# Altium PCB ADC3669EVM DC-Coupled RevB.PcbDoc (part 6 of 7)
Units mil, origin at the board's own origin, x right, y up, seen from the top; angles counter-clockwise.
Board outline 5000 x 2716.54 mil, 12 copper layers (Top Layer, L2 GND, L3 SIG, L4 GND, L5 PWR, L6 GND, L7 GND, L8 PWR, L9 GND, L10 PWR, L11 GND, Bottom Layer), stack 61 mil thick; 546 components, 341 nets, 2088 pads, 1256 vias.
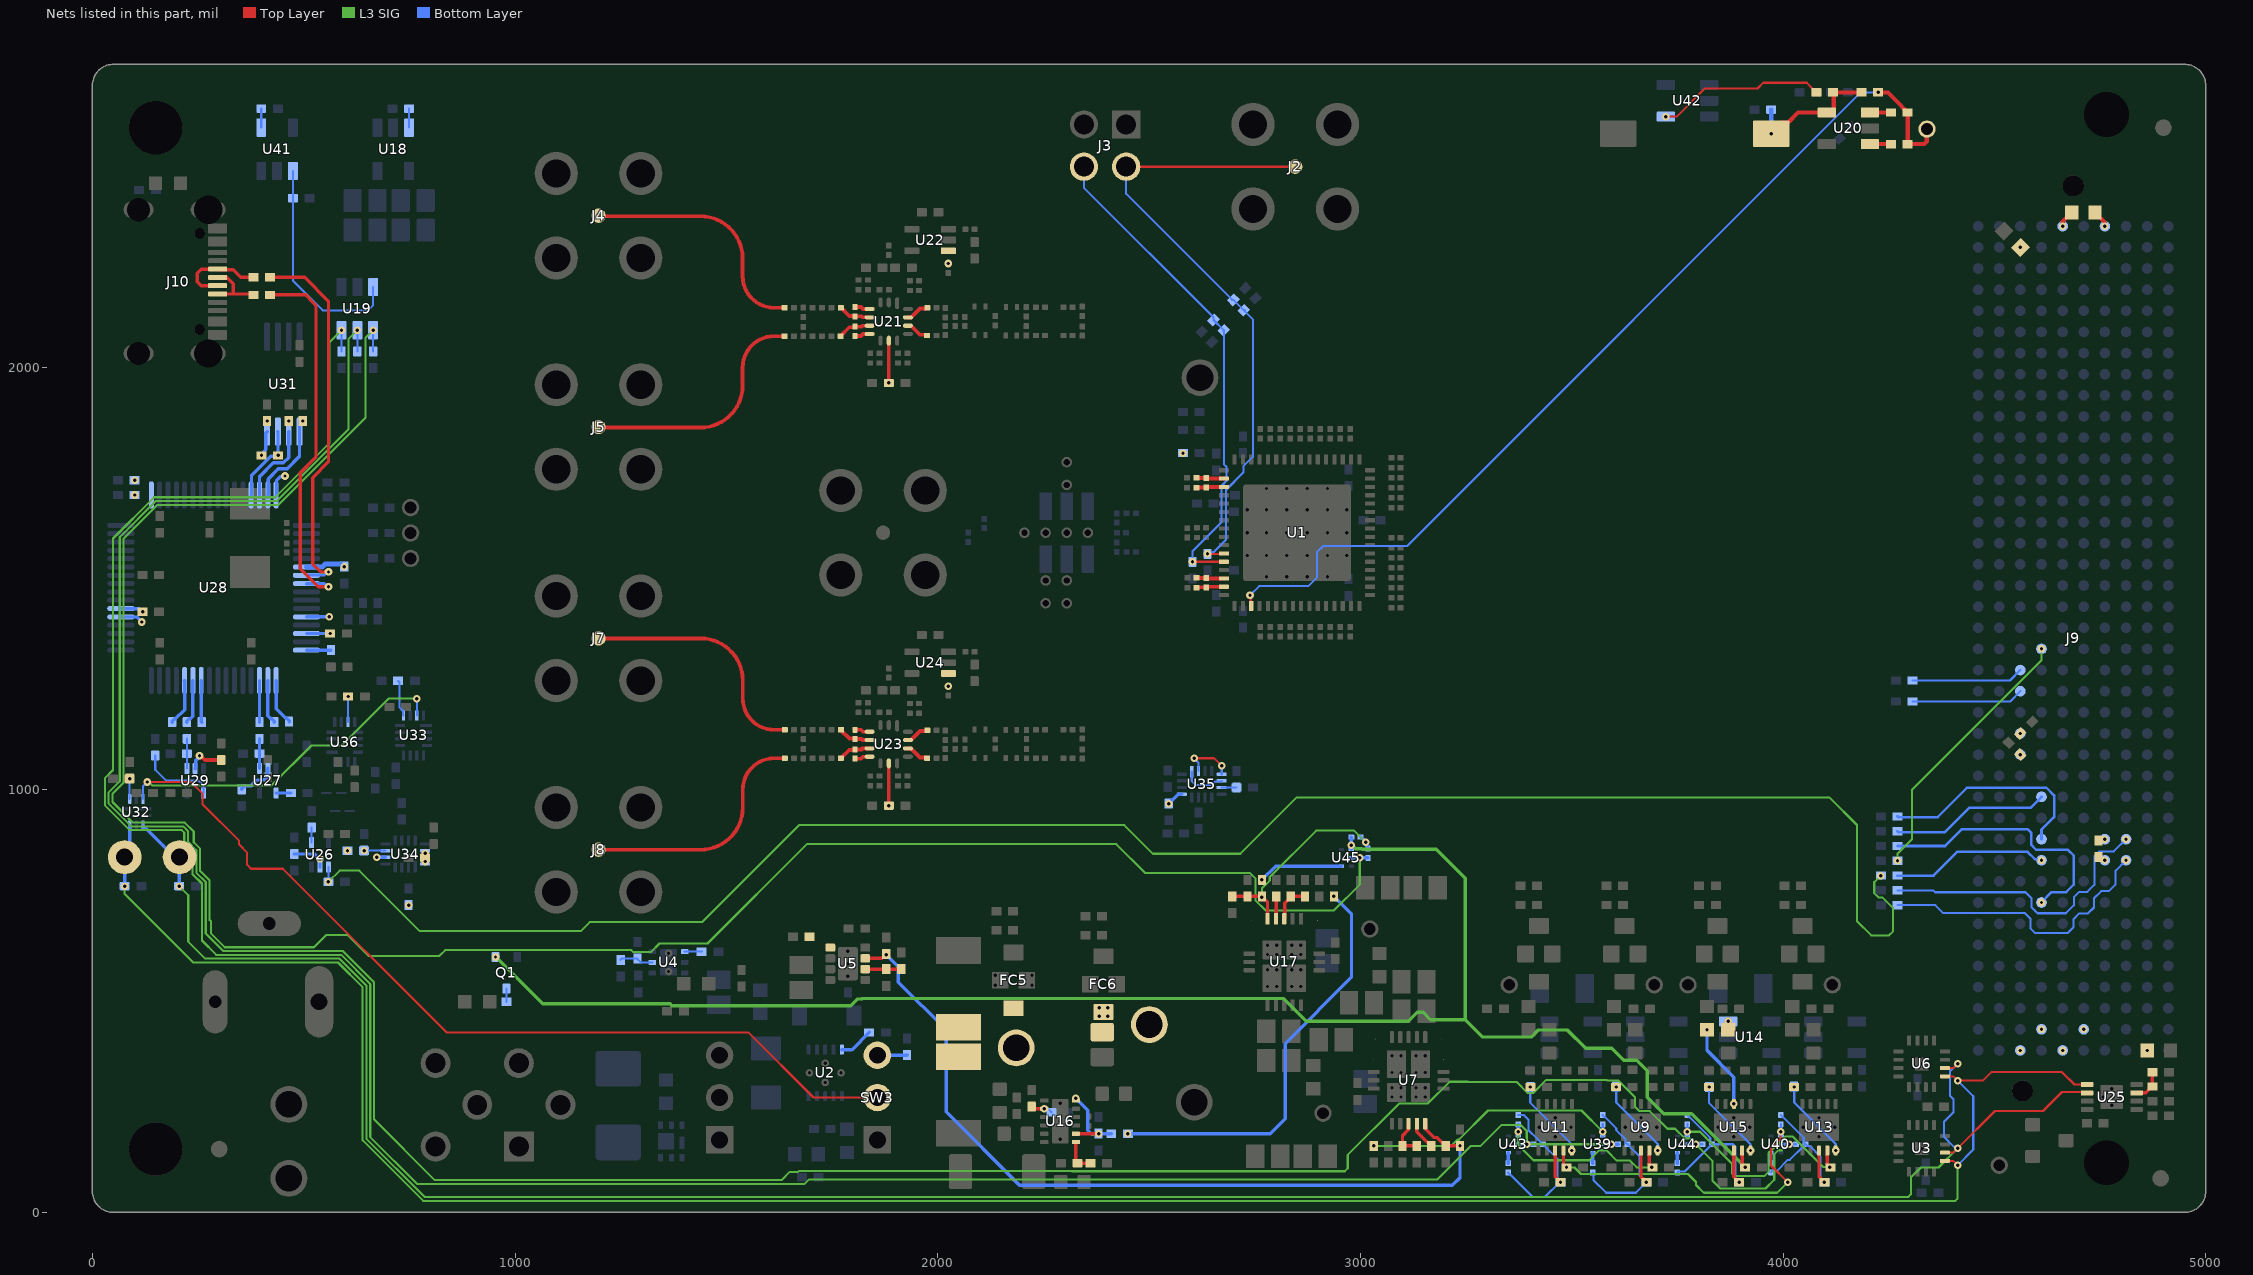
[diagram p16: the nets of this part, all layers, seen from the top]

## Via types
v1: diameter 18, hole 8, Top Layer to Bottom Layer, tented both sides, 1256 vias

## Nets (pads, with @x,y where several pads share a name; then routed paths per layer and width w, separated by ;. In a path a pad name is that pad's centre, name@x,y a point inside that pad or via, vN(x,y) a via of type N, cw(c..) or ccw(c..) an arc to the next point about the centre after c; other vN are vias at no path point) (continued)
NetFB6_1: FB6.1 R46.1 U14.3 U15.8 | length 221.5
  Top Layer w18: R46.1@3870.14,432.35 v1(3870.14,452.04)
  Bottom Layer w8: v1(3820.14,432.35) 3820.14,383.17 3883.53,319.79 v1(3883.53,256.76)
NetFC5_1: FC5.1 R54.1 R58.2 TP9.1
NetFC6_1: FC6.1 R59.2 TP8.1
  other v1: 2382,464.15 2402,464.15 2382,484.15 2402,484.15
NetJ2_1: J2.1 J3.2 R111.1 R112.2 R122.1 U1.27 | length 1534.2
  Top Layer w5: J3.2@2445.89,2474.15 J2.1@2845.89,2474.15 ; v1(2638.33,1558.27) 2675.98,1558.27 U1.27@2676.77,1559.06
  Bottom Layer w5: J3.2@2445.89,2474.15 2445.89,2409.81 2696.65,2159.05 R112.2@2699.5,2159.05 R122.1@2723.77,2134.78 ; v1(2638.33,1558.27) 2642.74,1562.68 2652.74,1562.68 2681.87,1591.81 2681.87,1709.17 2723.23,1750.53 2723.23,1765.27 2745.57,1787.61 2745.57,2112.98 R122.1@2723.77,2134.78 ; R122.1@2727.22,2134.78 R122.1@2723.77,2134.78
NetJ3_4: J3.4 R113.2 R121.2 R123.1 U1.28 | length 1181.2
  Top Layer w5: v1(2602.87,1539.37) U1.28@2676.77,1539.37
  Bottom Layer w5: J3.4@2345.89,2474.15 2345.89,2424.15 2652.34,2117.7 R123.1@2652.34,2111.49 R113.2@2676.61,2087.22 R113.2@2676.61,2084.44 ; v1(2602.87,1539.37) 2602.87,1564.5 2671.27,1632.89 2671.27,1718.86 2683.35,1730.94 2683.35,1764.05 2677.03,1770.36 R113.2@2677.03,2084.01
NetJ4_1: J4.1 R147.1 | length 581.1
  Top Layer w9: J4.1@1198.17,2356.89 1438.46,2356.89 cw(c1438.46,2256.89) 1538.46,2256.89 1538.46,2214.96 ccw(c1612.83,2214.96) 1612.83,2140.59 R147.1@1637.78,2140.59
NetJ5_1: J5.1 R140.1 | length 581.1
  Top Layer w9: J5.1@1198.17,1856.89 1438.46,1856.89 ccw(c1438.46,1956.89) 1538.46,1956.89 1538.46,1998.82 cw(c1612.83,1998.82) 1612.83,2073.19 R140.1@1637.78,2073.19
NetJ7_1: J7.1 R166.1 | length 582.1
  Top Layer w9: J7.1@1197.5,1358.27 1438.86,1358.27 cw(c1438.86,1258.27) 1538.86,1258.27 1538.86,1216.34 ccw(c1613.23,1216.34) 1613.23,1141.97 R166.1@1638.18,1141.97
NetJ8_1: J8.1 R159.1 | length 582.1
  Top Layer w9: J8.1@1197.5,858.27 1438.86,858.27 ccw(c1438.86,958.27) 1538.86,958.27 1538.86,1000.2 cw(c1613.23,1000.2) 1613.23,1074.57 R159.1@1638.18,1074.57
NetJ9_B40: J9.B40 R182.2
  other v1: 4861.42,383.27
NetJ9_C30: J9.C30 R180.2 | length 698.8
  Bottom Layer w5: R180.2@4270.69,762 4355.65,762 4360.11,757.54 4573.56,757.54 4587.87,743.23 4587.87,722.12 4602.07,707.92 4669.02,707.92 4688.01,726.9 4688.01,745.91 4700.55,758.45 4719.92,758.45 4736.51,775.05 4736.51,842.58 4748.32,854.39 4782.54,854.39 v1(4811.42,883.27)
NetJ9_C31: J9.C31 R181.2 | length 695.4
  Bottom Layer w5: R181.2@4270.69,727 4360.05,727 4378.74,708.31 4572.43,708.31 4585.17,695.57 4585.17,672.37 4596.73,660.8 4673,660.8 4686.96,674.76 4686.96,693.63 4700.89,707.56 4721.5,707.56 4735.57,721.63 4735.57,743.09 4752.76,760.28 4770.22,760.28 4786.67,776.73 4786.67,808.52 v1(4811.42,833.27)
NetJ9_G21: J9.G21 R193.2 | length 642.4
  L3 SIG w5: v1(4270.69,832) 4270.69,848.85 4305.1,883.27 4305.1,999.72 4611.42,1306.04 v1(4611.42,1333.27)
NetJ9_G28: J9.G28 R199.2 | length 376.1
  Bottom Layer w6: R199.2@4270.69,902 4272.69,900 4382.92,900 4440.92,958 4586.15,958 J9.G28@4611.42,983.27
NetJ9_G30: J9.G30 R200.2 | length 523.3
  Bottom Layer w6: R200.2@4270.69,937 4272.69,935 4365.42,935 4435.18,1004.76 4622.95,1004.76 4641.06,986.65 4641.06,935.19 4611.42,905.55 J9.G30@4611.42,883.27
NetJ9_G31: J9.G31 R201.2 | length 372
  Bottom Layer w6: R201.2@4270.69,797 4356.13,797 4411.99,852.87 4578.47,852.87 4595.47,835.87 4608.82,835.87 v1(4611.42,833.27)
NetJ9_G33: J9.G33 R204.2 | length 639.1
  Bottom Layer w6: R204.2@4270.69,867 4383.35,867 4423.35,907 4578.32,907 4587.39,897.93 4587.39,869.48 4598.99,857.88 4674.03,857.88 4687.68,844.24 4687.68,775.48 4669.92,757.73 4635.17,757.73 4611.42,733.97 v1(4611.42,733.27)
NetJ9_H22: J9.H22 R194.2 | length 265.6
  Bottom Layer w5: R194.2@4306.05,1258.67 4536.82,1258.67 J9.H22@4561.42,1283.27
NetJ9_H23: J9.H23 R195.2 | length 265.6
  Bottom Layer w5: R195.2@4306.05,1208.67 4536.82,1208.67 J9.H23@4561.42,1233.27
NetJ9_H25: J9.H25 R197.2
  other v1: 4561.42,1133.27
NetJ9_H26: J9.H26 R198.2
  other v1: 4561.42,1083.27
NetJ10_A6: J10.A6 J10.B6 R229.1 | length 152.8
  Top Layer w8: J10.B6@296.46,2172.91 333.53,2172.91 ; J10.A6@296.46,2212.28 318.29,2212.28 333.53,2197.03 333.53,2172.91 ; R229.1@380.82,2170.78 378.69,2172.91 333.53,2172.91
NetJ10_A7: J10.A7 J10.B7 R227.1 | length 217.6
  Top Layer w8: J10.A7@296.46,2192.59 257.49,2192.59 248.12,2201.97 248.12,2222.59 257.49,2231.96 J10.B7@296.46,2231.96 298.36,2230.06 333.53,2230.06 351.31,2212.28 R227.1@380.82,2212.28
NetL1_2: L1.2 R131.2 U1.18 | length 64.4
  Top Layer w9: L1.2@2612.27,1737.9 2634.77,1737.9 R131.2@2635.27,1737.4 R131.2@2635.86,1736.81 ; R131.2@2636.45,1736.22 U1.18@2676.77,1736.22
NetL2_2: L2.2 R131.1 U1.19 | length 65.2
  Top Layer w9: L2.2@2612.27,1714.86 2634.77,1714.86 R131.1@2635.27,1715.36 2636.45,1716.54 U1.19@2676.77,1716.54
NetL3_2: L3.2 R136.2 U1.31 | length 64.7
  Top Layer w9: L3.2@2612.77,1478.35 cw(c2614.67,1476.45) 2614.67,1479.14 R136.2@2635.27,1479.14 2636.45,1480.32 U1.31@2676.77,1480.32
NetL4_2: L4.2 R136.1 U1.30 | length 64.7
  Top Layer w9: L4.2@2612.77,1501.97 ccw(c2614.67,1503.87) 2614.67,1501.18 R136.1@2635.27,1501.18 ; R136.1@2634.68,1501.77 R136.1@2635.27,1501.18 ; R136.1@2635.86,1500.59 R136.1@2635.27,1501.18 ; R136.1@2636.45,1500 U1.30@2676.77,1500
NetPP11_1: PP11.1 R124.1 R127.1 R128.1 U1.35 | length 2283.7
  Top Layer w5: v1(2738.73,1460.04) 2740.54,1458.23 2740.54,1436.23 U1.35@2741.73,1435.04
  Top Layer w10: v1(4224.84,2650) 4247.91,2650 4280.29,2617.63 4280.29,2616.96 4292.03,2605.21 4292.03,2603.24 4292.88,2602.4 R128.1@4294.84,2602.4 R127.1@4294.84,2527.6 4333.99,2527.6 4339.84,2533.46 4339.84,2562.4 PP11.1@4340.47,2563.03
  Bottom Layer w5: v1(2738.73,1460.04) 2760.42,1481.73 2876.73,1481.73 2897,1502 2897,1562 2911.9,1576.9 3110.9,1576.9 4184,2650 v1(4224.84,2650)
NetQ1_3: Q1.3 R1.2 | length 31.2
  Bottom Layer w5: R1.2@979.47,498.46 Q1.3@979.47,529.7
NetR4_2: R4.2 U2.10 | length 81.5
  Bottom Layer w8: U2.10@1773.24,385.32 1797.26,385.32 R4.2@1837.89,425.96
NetR7_1: R7.1 U5.1
NetR8_1: R8.1 U4.4 | length 40.1
  Bottom Layer w5: U4.4@1401.56,617.17 1441.57,617.17 R8.1@1441.61,617.12
NetR9_1: R9.1 R11.2 U4.2 | length 81.4
  Bottom Layer w5: R9.1@1249.79,597.8 1253.03,601.04 R11.2@1289.77,601.04 1289.77,599.07 1297.11,591.73 1324.64,591.73 U4.2@1324.79,591.58
NetR10_1: R10.1 R12.2 U5.6 | length 85
  Top Layer w9: U5.6@1828.52,575.52 R10.1@1878.52,575.52 R12.2@1913.52,575.52
NetR15_2: R15.2 U7.23 | length 68.1
  Top Layer w8: U7.23@3133.63,210.25 3133.63,191.44 3159.83,165.24 3161.8,165.24 3167.64,159.4 R15.2@3167.64,157.43
NetR16_1: R16.1 R18.2 U7.22 | length 92.7
  Top Layer w8: U7.22@3113.94,210.25 3113.02,209.33 3113.02,195.14 3099.64,181.75 R16.1@3099.64,157.43 R18.2@3133.64,157.43
NetR21_1: R21.1 R24.2 U9.5 | length 191
  Bottom Layer w5: v1(3605.22,296.76) 3605.22,260.2 3703.42,161.99 3703.42,146.8 v1(3703.14,146.52)
NetR22_1: R22.1 R23.1 R26.2 R63.2 R71.2 U9.3 | length 451.1
  Top Layer w8: U9.3@3663.77,146.52 3663.77,84.12 3668.56,79.33 3668.56,77.37 3674.4,71.52 v1(3676.37,71.52)
  Bottom Layer w5: R23.1@3549.82,94.56 3551.29,93.09 3551.29,76.93 3581.69,46.52 3651.37,46.52 3667.06,62.21 3667.06,64.18 R26.2@3674.4,71.52 ; R63.2@3573.44,230.66 3573.44,229.87 3578.44,224.87 3579.23,224.87 3605.22,198.88 3605.22,194.89 3627.12,172.99 3627.12,165.26 3630.92,161.47 R71.2@3631.71,161.47 3632.5,161.47 3637.5,156.47 3637.5,155.68 3660.62,132.55 3660.62,87.27 3667.06,80.83 3667.06,78.87 R26.2@3674.4,71.52 ; v1(3676.37,71.52) R26.2@3674.4,71.52
NetR23_2: R23.2 U39.4 | length 25
  Bottom Layer w8: R23.2@3549.82,116.6 U39.4@3549.82,141.6
NetR30_1: R30.1 R33.2 U11.5 | length 191.2
  Bottom Layer w5: v1(3402.29,296.76) 3401.79,296.26 3401.79,259.89 3500.21,161.47 v1(3500.21,146.52)
NetR31_1: R31.1 R32.1 R34.2 R81.2 R110.2 U11.3 | length 442.6
  Top Layer w8: U11.3@3460.84,146.52 3460.84,84.12 3465.63,79.33 R31.1@3465.63,77.37
  Bottom Layer w5: R32.1@3349.82,94.56 3349.82,93.77 3354.82,88.77 3355.61,88.77 3407.85,36.52 3436.47,36.52 R34.2@3471.47,71.52 ; R81.2@3373.44,230.66 3386.83,230.66 3397.46,220.03 3397.46,195 3418.19,174.26 3418.7,174.26 3425.92,167.05 3425.92,166.47 3430.92,161.47 R110.2@3431.71,161.47 3432.5,161.47 3437.5,156.47 3437.5,155.68 3465.76,127.42 3465.76,77.24 R34.2@3471.47,71.52 ; v1(3473.44,71.52) R34.2@3471.47,71.52
NetR32_2: R32.2 U43.4 | length 25
  Bottom Layer w8: R32.2@3349.82,116.6 U43.4@3349.82,141.6
NetR38_1: R38.1 R41.2 U13.5 | length 191
  Bottom Layer w5: v1(4026.53,296.76) 4026.53,260.2 4124.73,161.99 4124.73,146.8 v1(4124.45,146.52)
NetR39_1: R39.1 R40.1 R43.2 R72.2 R76.2 U13.3 | length 398.7
  Top Layer w8: U13.3@4085.08,146.52 4085.08,84.12 4089.87,79.33 4089.87,77.37 4095.71,71.52 v1(4097.68,71.52)
  Bottom Layer w5: R40.1@3971.13,94.56 3971.13,95.1 3974.93,98.9 3985.88,98.9 4011.42,124.44 4015.99,124.44 4048.34,156.79 4048.34,157.58 4052.14,161.38 R76.2@4052.73,161.38 ; R72.2@3994.75,230.66 3994.75,229.87 3999.75,224.87 4000.54,224.87 4048.94,176.48 4048.94,165.18 R76.2@4052.73,161.38 ; v1(4097.68,71.52) 4095.71,71.52 4088.37,78.87 4088.37,132.45 4063.24,157.58 4056.73,157.58 R76.2@4052.93,161.38 R76.2@4052.73,161.38
NetR40_2: R40.2 U40.4 | length 25
  Bottom Layer w8: R40.2@3971.13,116.6 U40.4@3971.13,141.6
NetR47_1: R47.1 R50.2 U15.5 | length 191.2
  Bottom Layer w5: v1(3824.97,296.76) 3824.47,296.26 3824.47,259.89 3922.9,161.47 v1(3922.9,146.52)
NetR48_1: R48.1 R49.1 R51.2 R116.2 R272.2 U15.3 | length 431.7
  Top Layer w8: U15.3@3883.53,146.52 3883.53,84.12 3888.31,79.33 3888.31,77.37 3894.16,71.52 v1(3896.12,71.52)
  Bottom Layer w5: R49.1@3749.82,94.56 3751.88,96.61 3766.86,96.61 3827.03,156.79 3827.03,157.58 3830.83,161.38 R272.2@3831.42,161.38 ; R116.2@3773.44,230.66 3773.44,229.87 3778.44,224.87 3779.23,224.87 3827.63,176.48 3827.63,165.18 R272.2@3831.42,161.38 ; v1(3896.12,71.52) 3895.05,71.52 3887.7,78.87 3887.7,155.52 3881.85,161.38 R272.2@3831.42,161.38
NetR49_2: R49.2 U44.4 | length 25
  Bottom Layer w8: R49.2@3749.82,116.6 U44.4@3749.82,141.6
NetR53_1: R53.1 R56.2 U16.7 | length 82.5
  Top Layer w8: U16.7@2326.95,166.54 2326.95,120.11 R53.1@2330.52,116.54 R56.2@2361.52,116.54
NetR55_1: R55.1 R57.2 U16.2 | length 52.5
  Top Layer w8: R57.2@2222.15,250.28 2227.15,245.28 v1(2252.15,245.28)
  Bottom Layer w5: v1(2252.15,245.28) 2253.57,243.85 2262.39,243.85 R55.1@2269.19,237.05
NetR60_2: R60.2 R65.1 R66.1 R69.2 R77.2 U17.24 | length 504.2
  Top Layer w8: R69.2@2696.94,748.05 R69.2@2697.04,747.95 2732.79,747.95 R65.1@2733,747.74 2765.03,747.74 R66.1@2767,745.77 ; R66.1@2767,747.74 v1(2767,745.95) R66.1@2767,745.77 ; U17.24@2780.32,694.92 2780.32,734.42 2774.81,739.93 2772.84,739.93 R66.1@2767,745.77
  L3 SIG w5: v1(2767,745.95) 2767,766.6 2785.5,785.1 2785.5,793.53 2895.4,903.44 2985.16,903.44 v1(3012.49,876.11)
  Bottom Layer w8: R60.2@3000.44,888.13 3001.22,888.13 3009.22,880.13 3009.22,879.37 3015.75,872.85 3015.75,863.51 R77.2@3018.05,861.21
NetR61_1: R61.1 U18.3 | length 45
  Bottom Layer w5: U18.3@749.15,2566.54 R61.1@749.15,2611.54
NetR62_1: R62.1 U41.4 | length 45
  Bottom Layer w5: U41.4@399.54,2566.54 R62.1@399.54,2611.54
NetR66_2: R66.2 U45.4 | length 201.1
  Bottom Layer w8: v1(2767,787.11) 2799.28,819.39 U45.4@2954.77,819.39
NetR67_2: R67.2 U17.23 | length 53.2
  Top Layer w8: U17.23@2800.01,694.92 2800.5,695.42 2800.5,747.24 R67.2@2801,747.74
NetR68_1: R68.1 R70.2 U17.22 | length 93.2
  Top Layer w8: U17.22@2819.69,694.92 2820.61,695.85 2820.61,731.39 2835,745.77 R68.1@2835,747.74 R70.2@2869,747.74
NetR73_1: R73.1 R74.1 R75.2 U16.8 U16.12 | length 204.4
  Top Layer w8: U16.8@2326.95,186.23 v1@2380.54,186.23 ; U16.12@2326.95,264.97 v1(2326.95,269.97)
  Bottom Layer w8: v1(2326.95,269.97) 2354.79,242.13 2354.79,194.89 2363.17,186.51 v1(2380.54,186.51) R74.1@2410.54,186.51
NetR78_2: R78.2 U19.3 U41.1 | length 526.5
  Bottom Layer w5: U41.1@474.35,2464.17 474.35,2204.98 544.95,2134.37 652.12,2134.37 664.25,2146.51 U19.3@664.25,2189.6
NetR79_1: R79.1 R80.2 U26.2 | length 85.1
  Bottom Layer w8: R79.1@477.93,848.07 524.85,848.07 535.81,837.1 v1(538.52,837.1) U26.2@538.52,817.1
NetR124_2: R124.2 R125.1 R126.1 SW2.1 U20.4 | length 336.4
  Top Layer w10: v1(3971.85,2552.4) 3998.34,2578.9 4012.09,2578.9 4035.6,2602.4 U20.4@4103.11,2602.4 4109.88,2602.4 4112.7,2605.21 4115.77,2605.21 4119.77,2609.21 R126.1@4119.77,2650 ; R126.1@4118.11,2650 R126.1@4119.77,2650 ; R124.2@4185.47,2650 R126.1@4119.77,2650
  Bottom Layer w10: v1(3971.85,2552.4) R125.1@3971.85,2609.21
NetR126_2: R126.2 U42.4 | length 400
  Top Layer w5: v1(3722.64,2592.6) 3748.57,2592.6 3815,2659.03 3939.45,2659.03 3953.29,2672.86 4055.88,2672.86 4069.43,2659.31 4069.43,2657.34 4076.77,2650 R126.2@4078.74,2650
NetR127_2: R127.2 U20.1 | length 50
  Top Layer w10: U20.1@4205.47,2527.6 R127.2@4255.47,2527.6
NetR128_2: R128.2 U20.3 | length 50
  Top Layer w10: U20.3@4205.47,2602.4 R128.2@4255.47,2602.4
NetR141_2: R141.2 R142.1 U21.6 | length 78
  Top Layer w9: R141.2@1770.53,2074.93 1771.31,2074.93 1790.86,2094.47 1803.17,2094.47 1804.25,2095.55 1819.82,2095.55 1822.11,2097.84 1838.81,2097.84 U21.6@1838.97,2098
NetR142_2: R142.2 U21.7 | length 36.7
  Top Layer w9: R142.2@1804.25,2073.51 1804.29,2073.54 1818.74,2073.54 1823.34,2078.15 1838.81,2078.15 U21.7@1838.97,2078.31
NetR143_1: R143.1 U21.13 | length 55.3
  Top Layer w9: U21.13@1929.53,2117.68 1936.64,2117.68 1957.91,2138.95 1973.45,2138.95 R143.1@1975.25,2140.75
NetR148_2: R148.2 R149.1 U21.5 | length 78
  Top Layer w9: R148.2@1770.53,2140.75 1771.31,2140.75 1790.86,2121.21 1803.17,2121.21 1804.25,2120.13 1819.82,2120.13 1822.11,2117.84 1838.81,2117.84 U21.5@1838.97,2117.68
NetR149_2: R149.2 U21.4 | length 36.7
  Top Layer w9: R149.2@1804.45,2141.97 R149.2@1804.45,2141.97 1818.9,2141.97 1823.5,2137.37 U21.4@1838.97,2137.37 U21.4@1839.14,2137.21
NetR150_1: R150.1 U21.12 | length 55
  Top Layer w9: U21.12@1929.53,2098 1936.64,2098 1957.91,2076.73 1973.15,2076.73 R150.1@1974.95,2074.93
NetR153_1: R153.1 R157.2 U21.9 | length 100
  Top Layer w9: v1(1884.25,1962.56) U21.9@1884.25,2062.56
NetR160_2: R160.2 R161.1 U23.6 | length 78
  Top Layer w9: R160.2@1770.53,1074.93 1771.31,1074.93 1790.86,1094.47 1803.17,1094.47 1804.25,1095.55 1819.82,1095.55 1822.11,1097.84 1838.81,1097.84 U23.6@1838.97,1098
NetR161_2: R161.2 U23.7 | length 36.7
  Top Layer w9: R161.2@1804.25,1073.51 1804.29,1073.54 1818.74,1073.54 1823.34,1078.15 1838.81,1078.15 U23.7@1838.97,1078.31
NetR162_1: R162.1 U23.13 | length 55.3
  Top Layer w9: U23.13@1929.53,1117.68 1936.64,1117.68 1957.91,1138.95 1973.45,1138.95 R162.1@1975.25,1140.75
NetR167_2: R167.2 R168.1 U23.5 | length 78
  Top Layer w9: R167.2@1770.69,1140.59 1771.47,1140.59 1791.02,1121.05 1803.33,1121.05 R168.1@1804.41,1119.97 1819.98,1119.97 1822.27,1117.68 U23.5@1838.97,1117.68 U23.5@1839.14,1117.52
NetR168_2: R168.2 U23.4 | length 36.7
  Top Layer w9: R168.2@1804.41,1142.01 R168.2@1804.41,1142.01 1818.9,1141.97 1823.5,1137.37 U23.4@1838.97,1137.37 U23.4@1839.14,1137.21
NetR169_1: R169.1 U23.12 | length 55
  Top Layer w9: U23.12@1929.53,1098 1936.64,1098 1957.91,1076.73 1973.15,1076.73 R169.1@1974.95,1074.93
NetR172_1: R172.1 R176.2 U23.9 | length 100
  Top Layer w9: v1(1884.25,962.56) U23.9@1884.25,1062.56
NetR178_1: R178.1 R179.2 U27.2 | length 94.1
  Bottom Layer w8: R178.1@353.29,1001.11 353.29,1003.07 359.13,1008.92 375.19,1008.92 389.48,1023.2 405.75,1023.2 415.12,1032.58 U27.2@415.07,1050.63 U27.2@415.07,1050.63
NetR184_1: R184.1 R187.2 U25.3 | length 78.4
  Top Layer w8: U25.3@4836.47,282.98 4858.47,282.98 4865.66,290.17 4865.66,292.14 4871.5,297.98 R184.1@4873.47,297.98 R187.2@4873.47,331.98
NetR189_1: R189.1 R190.2 U29.2 | length 89.9
  Top Layer w9: v1(253.33,1080.63) 255.76,1080.63 265.91,1070.48 R190.2@304.91,1070.48
  Bottom Layer w9: U29.2@243.33,1050.63 244.73,1052.04 244.73,1069.6 253.33,1078.19 v1(253.33,1080.63)
NetR201_1: R201.1 R207.2 U26.1 | length 4429.3
  L3 SIG w5: v1(558.2,782.1) 584.9,808.8 631.8,808.8 774.87,665.73 1155.73,665.73 1176.78,686.78 1442.22,686.78 1671.85,916.41 2441.24,916.41 2509.12,848.54 2715.99,848.54 2849.51,982.06 4109.43,982.06 4174.96,916.53 4174.96,688.83 4208.35,655.43 4250.58,655.43 4260.37,665.22 4260.37,719.87 4234.74,745.49 4225.9,745.49 4215.81,755.58 4215.81,781.5 v1(4231.31,797)
  Bottom Layer w5: v1(558.2,782.1) U26.1@558.2,817.1
NetR208_1: R208.1 U26.4 | length 35
  Bottom Layer w5: U26.4@518.83,875.37 R208.1@518.83,910.37
NetR210_2: R210.2 R215.2 U27.1 | length 70
  Bottom Layer w8: U27.1@395.38,1050.63 R210.2@395.38,1085.63 R215.2@395.38,1120.63
NetR211_1: R211.1 U27.4 | length 35
  Bottom Layer w8: U27.4@434.75,992.36 R211.1@469.75,992.36
NetR212_1: R212.1 U28.16 | length 57.8
  Bottom Layer w8: U28.16@506.6,1330.34 R212.1@564.43,1330.34
NetR213_1: R213.1 U28.17 | length 111.3
  Bottom Layer w8: U28.17@434.75,1258.49 434.75,1191.61 457.57,1168.8 459.54,1168.8 465.38,1162.95 R213.1@465.38,1160.98
NetR214_1: R214.1 U28.18 | length 106
  Bottom Layer w8: U28.18@415.07,1258.49 415.07,1175.31 422.57,1167.81 424.54,1167.81 430.38,1161.97 R214.1@430.38,1160
NetR215_1: R215.1 U28.19 | length 98.5
  Bottom Layer w8: R215.1@395.38,1160 U28.19@395.38,1258.49
NetR218_1: R218.1 U28.26 | length 98.9
  Bottom Layer w8: U28.26@257.59,1258.49 257.59,1161.05 R218.1@258.64,1160
NetR219_1: R219.1 U28.27 | length 106.6
  Bottom Layer w8: R219.1@223.64,1160 223.64,1161.97 229.49,1167.81 231.45,1167.81 237.9,1174.26 U28.27@237.9,1258.49 U28.27@237.17,1257.76
NetR220_1: R220.1 U28.28 | length 112.9
  Bottom Layer w8: R220.1@188.64,1160 188.64,1161.97 194.49,1167.81 196.45,1167.81 218.22,1189.57 U28.28@218.22,1258.49 U28.28@217.49,1257.76
NetR221_1: R221.1 U29.4 | length 181.9
  Bottom Layer w5: R221.1@148.64,1081.26 148.64,1047.36 174.5,1021.5 252.32,1021.5 263.01,1010.81 U29.4@263.01,992.36
NetR222_1: R222.1 U28.38 | length 54.3
  Bottom Layer w8: U28.38@67.63,1428.77 67.72,1428.67 109.55,1428.67 117.14,1421.08 v1(118.77,1421.08)
NetR224_1: R224.1 U28.14 | length 55.9
  Bottom Layer w8: U28.14@506.6,1369.71 v1(562.53,1369.71)
NetR227_2: R227.2 U28.7 | length 899
  Top Layer w8: R227.2@420.19,2212.28 502.19,2212.28 558.56,2155.91 558.56,1775.58 521.46,1738.47 521.46,1534.04 540.12,1515.38 v1(558.56,1515.38)
  Bottom Layer w8: U28.7@506.6,1507.51 507.33,1508.23 548.71,1508.23 555.86,1515.38 v1(558.56,1515.38)
NetR229_2: R229.2 U28.8 | length 898.2
  Top Layer w8: R229.2@420.19,2170.78 504.53,2170.78 521.46,2153.85 521.46,2153.49 528.94,2146.01 528.94,1787.01 491.38,1749.45 491.38,1522.73 534.16,1479.95 v1(558.56,1479.95)
  Bottom Layer w8: U28.8@506.6,1487.82 507.33,1487.09 548.71,1487.09 555.86,1479.95 v1(558.56,1479.95)
NetR240_2: R240.2 U28.6 | length 95
  Bottom Layer w12: U28.6@506.6,1527.19 506.7,1527.28 543.6,1527.28 550.69,1534.38 587.89,1534.38 594.32,1527.96 v1(595.94,1527.96)
NetR241_1: R241.1 U28.62 U31.2 | length 192.4
  Bottom Layer w8: U28.62@395.38,1697.47 395.38,1740.36 428.41,1773.38 451.92,1773.38 464.48,1785.94 U31.2@464.48,1847.47
  other v1: 464.48,1872.47
NetR242_1: R242.1 R244.1 U31.4 | length 61.9
  Bottom Layer w8: v1(400.19,1791.02) 400.19,1793.73 410.41,1803.95 410.41,1844.58 U31.4@413.3,1847.47
  other v1: 413.3,1872.47
NetR243_1: R243.1 U28.63 U31.1 | length 224.5
  Bottom Layer w8: U28.63@415.07,1697.47 415.8,1698.2 415.8,1735.3 439.98,1759.48 460.61,1759.48 490.07,1788.94 U31.1@490.07,1847.47 490.07,1869.58 492.96,1872.47 v1(498.07,1872.47)
NetR244_2: R244.2 U28.61 U31.3 | length 185.7
  Bottom Layer w8: U28.61@375.7,1697.47 376.43,1698.2 376.43,1743.22 422.56,1789.35 437.89,1789.35 v1(439.56,1791.02) 439.22,1791.36 439.22,1847.13 U31.3@438.89,1847.47
NetR247_1: R247.1 R248.2 U32.8 | length 47.6
  Bottom Layer w5: U32.8@88.25,978.5 v1(88.25,1026.14)
NetR254_1: R254.1 SW3.2 | length 70.7
  Bottom Layer w8: SW3.2@1857.15,371.9 1857.46,372.21 1927.28,372.21 R254.1@1927.59,372.53
NetR255_1: R255.1 R256.2 U33.13 | length 87.3
  Bottom Layer w5: R255.1@723.46,1257.76 726.25,1254.98 726.25,1194.88 734.81,1186.32 734.81,1177.18 U33.13@736.25,1175.75
NetR257_1: R257.1 R263.2 U35.7 | length 35
  Bottom Layer w5: U35.7@2671.9,1005.26 R257.1@2706.9,1005.26
NetR258_1: R258.1 R262.2 U34.7 | length 50
  Bottom Layer w5: v1(642.94,855.94) U34.7@692.94,855.94
NetR264_1: R264.1 R267.2 U36.7 | length 60.7
  Bottom Layer w5: U36.7@604.75,1160 604.75,1220.12 v1(605.19,1220.56)
NetSW3_1: SW3.1 U32.10 U33.15 | length 2884.4
  Top Layer w5: v1(129.75,1018.5) 233.11,1018.5 260.16,991.45 260.16,966.47 347.07,879.55 347.07,870.63 366.26,851.44 366.26,822.38 375.34,813.3 450.37,813.3 837.71,425.96 1552.12,425.96 1706.17,271.9 SW3.1@1857.15,271.9
  L3 SIG w5: v1(129.75,1018.5) 133.27,1018.5 141.79,1009.97 423.39,1009.97 518.3,1104.88 589.84,1104.88 700.71,1215.75 v1(767.74,1215.75)
  Bottom Layer w5: U32.10@119.75,978.5 119.75,1008.5 v1(129.75,1018.5) ; U33.15@767.74,1175.75 v1(767.74,1215.75)
NetU35_1: U35.1 U35.6 | length 100.7
  Bottom Layer w5: U35.1@2601.03,1042.66 2601.03,1020.58 2610.15,1011.46 2648.67,1011.46 2657.17,1019.96 2670.86,1019.96 U35.6@2671.9,1021.01
NetU35_2: U35.2 U35.5 | length 126.7
  Top Layer w5: v1(2606.78,1074.63) 2654.03,1074.63 v1(2671.9,1056.76)
  Bottom Layer w5: v1(2606.78,1074.63) 2616.78,1064.63 U35.2@2616.78,1044.63 ; U35.5@2671.9,1036.76 v1(2671.9,1056.76)
PG-C2M: J9.D1 R183.1 | length 41.9
  Top Layer w10: R183.1@4737.8,2365.39 4761.42,2341.76 v1(4761.42,2333.27)
PG-M2C: J9.F1 R183.2 | length 40.9
  Top Layer w10: v1(4661.42,2333.27) 4661.42,2344.13 R183.2@4682.68,2365.39
PRSNT-M2C-L: J9.H2 R192.2
  other v1: 4561.42,2283.27
PwrGd_3p3Gen: R6.1 R14.1 R17.2 U5.7 U7.24 | length 1968.9
  Top Layer w8: U5.7@1828.52,601.12 1867.99,601.12 1870.18,603.3 1872.67,603.3 1878.52,609.15 v1(1878.52,610.13) R6.1@1878.52,611.12 ; U7.24@3153.31,210.25 3154.24,209.33 3154.24,197.26 3174.25,177.24 3180.79,177.24 3181.05,176.99 3182.08,176.99 3193.83,165.24 3195.8,165.24 3201.64,159.4 R14.1@3201.64,157.43 v1(3235.64,157.43)
  Bottom Layer w8: v1(1878.52,610.13) 1906.78,581.87 1906.78,544.76 2019.77,431.77 2019.77,237.85 2193.44,64.18 3217.36,64.18 3235.64,82.46 v1(3235.64,157.43)
PwrGd_4p3V_LDO: R64.1 R74.2 U17.19 | length 994.7
  Bottom Layer w8: v1(2449.91,186.51) 2786.64,186.51 2821.8,221.67 2821.8,399.31 2978.83,556.34 2978.83,706.28 v1(2937.37,747.74)
PwrGd_Analog: R13.1 R63.1 U7.19 U39.1 | length 625.4
  L3 SIG w5: v1(3031.27,157.43) 3215.13,157.43 3229.63,171.93 3232.69,171.93 3302.02,241.26 3523.15,241.26 v1(3573.44,190.97)
  Bottom Layer w5: v1(3573.44,190.97) R63.1@3573.44,208.61
  Bottom Layer w8: U39.1@3573.44,180.97 v1(3573.44,190.97)
PwrGd_AVDD12: R28.1 R72.1 U11.4 U40.1 | length 779.5
  Top Layer w5: v1(3994.75,190.97) 3994.19,190.41 3994.19,174.06 3971.48,151.34 3971.48,111.11 v1(4011.07,71.52)
  Top Layer w8: U11.4@3480.53,146.52 3480.53,112.37 3486.37,106.52 v1(3487.61,106.52)
  L3 SIG w5: v1(3487.61,106.52) 3506.48,106.52 3521.91,91.09 3775.02,91.09 3794.01,72.1 3794.01,65.1 3812.59,46.52 3986.07,46.52 v1(4011.07,71.52)
  Bottom Layer w5: v1(3994.75,190.97) R72.1@3994.75,208.61
  Bottom Layer w8: U40.1@3994.75,180.97 v1(3994.75,190.97)
PwrGd_AVDD18: Q1.1 R45.1 R60.1 U15.4 U45.1 | length 3954.3
  Top Layer w8: U15.4@3903.21,146.52 3903.21,112.37 3909.05,106.52 v1(3910.3,106.52)
  L3 SIG w8: v1(953.88,604.5) 1065.05,493.33 1367.04,493.33 1370.93,489.44 1794.44,489.44 1809.97,504.97 1820.48,504.97 1821.8,506.29 2817.14,506.29 2871.44,452 3112.92,452 3134.23,473.31 3148.31,473.31 3165.31,456.31 3247.64,456.31 ; v1(2978.39,868.76) 2981.09,868.76 2989.02,860.83 3003.72,860.83 3005.44,859.11 3179.61,859.11 3247.64,791.08 3247.64,456.31 ; v1(3910.3,106.52) 3783.46,233.36 3717.46,233.36 3678.73,272.09 3678.73,335.25 3653.75,360.23 3623.07,360.23 3594.92,388.39 3532.74,388.39 3489.5,431.63 3420.78,431.63 3404.16,415.01 3288.94,415.01 3247.64,456.31
  Bottom Layer w8: U45.1@2978.39,858.76 v1(2978.39,868.76) R60.1@2978.39,888.13
PwrGd_DVDD12: R19.1 R81.1 U9.4 U43.1 | length 460.3
  Top Layer w5: R19.1@3690.54,106.52 R19.1@3690.84,106.52
  Top Layer w8: U9.4@3683.46,146.52 3683.46,112.37 v1(3689.23,106.59) 3689.3,106.52 R19.1@3690.54,106.52
  L3 SIG w5: v1(3373.44,190.97) 3373.44,159.56 3409.48,123.52 3541.52,123.52 3565.1,147.1 3582.18,147.1 3606.76,122.52 3637.99,122.52 3653.93,106.59 v1(3689.23,106.59)
  Bottom Layer w5: v1(3373.44,190.97) R81.1@3373.44,208.61
  Bottom Layer w8: U43.1@3373.44,180.97 v1(3373.44,190.97)
PwrGd_DVDD18: R36.1 R116.1 U13.4 U44.1 | length 560.1
  Top Layer w8: U13.4@4104.77,146.52 4104.77,112.37 v1(4110.61,106.52) R36.1@4111.85,106.52
  L3 SIG w5: v1(3773.44,190.97) 3803.49,190.97 3879.12,115.35 3879.12,93.01 3886.11,86.02 3955.79,86.02 3965.13,95.36 3965.13,139.43 4005.59,179.89 4022.36,179.89 4094.43,107.82 4109.31,107.82 v1(4110.61,106.52)
  Bottom Layer w5: v1(3773.44,190.97) R116.1@3773.44,208.61
  Bottom Layer w8: U44.1@3773.44,180.97 v1(3773.44,190.97)
SCL_I2C: R245.1 TP5.1 U3.14 U6.14 U25.6 U32.3 | length 5713
  Top Layer w5: U3.14@4382.92,141.6 4402.92,141.6 v1(4412.92,151.6) 4501.32,240 4615,240 4660,285 U25.6@4715,285 ; U6.14@4382.92,341.6 4402.92,341.6 v1(4412.92,351.6)
  L3 SIG w5: v1(205.33,772.13) 226.91,750.55 226.91,640.87 267.3,600.47 584.83,600.47 593.83,591.47 648.37,536.92 648.37,174.57 786.44,36.5 4296.27,36.5 4302.46,42.69 4302.46,82.75 4326.24,106.52 4367.84,106.52 v1(4412.92,151.6)
  Bottom Layer w5: v1(4412.92,151.6) 4409.4,151.6 4405.2,155.8 4403.79,155.8 4380.59,179 4380.59,214.23 4402.92,236.56 4402.92,268.4 4395,276.32 4395,333.68 v1(4412.92,351.6)
  Bottom Layer w8: U32.3@119.75,915.5 119.75,907.76 119.81,907.69 127.56,907.69 194.64,840.61 TP5.1@206.45,840.61 205.33,839.49 v1(205.33,772.13)
SDA_I2C: R246.1 TP6.1 U3.13 U6.13 U25.5 U32.5 | length 5723.4
  Top Layer w5: U3.13@4382.92,121.92 4402.92,121.92 v1(4412.92,111.92) ; U6.13@4382.92,321.92 4402.92,321.92 v1(4412.92,311.92) 4472.73,311.92 4492.8,331.98 4660,331.98 4689.31,302.67 U25.5@4719.22,302.67
  L3 SIG w5: v1(76.45,772.13) 76.45,753.36 238.34,591.47 581.1,591.47 639.37,533.2 639.37,170.84 782.71,27.5 4407.5,27.5 4412.92,32.92 v1(4412.92,111.92)
  Bottom Layer w5: v1(4412.92,111.92) 4450,149 4450,274.84 v1(4412.92,311.92)
  Bottom Layer w8: v1(76.45,772.13) TP6.1@76.45,840.61 88.25,852.41 U32.5@88.25,915.5
SDAw: R217.1 R219.2 U29.1 | length 70
  Bottom Layer w5: U29.1@223.64,1050.63 R217.1@223.64,1085.63 R219.2@223.64,1120.63
Seq_1p2V: R71.1 R110.1 R273.1 U19.6 U39.2 U43.2 | length 6012.8
  L3 SIG w5: v1(589.45,2087.24) 560.56,2058.36 560.56,1819.86 432.79,1692.09 146.5,1692.09 48.88,1594.48 48.88,1046.65 29.49,1027.26 29.49,963.48 88.57,904.4 211.41,904.4 217.27,898.54 217.27,872.93 236.95,853.24 236.95,800.38 259.2,778.13 259.2,643.32 293.05,609.47 588.56,609.47 657.37,540.65 657.37,178.3 768.17,67.5 1685.05,67.5 1695.87,78.32 3182.4,78.32 3261.51,157.43 3284.36,157.43 3333.4,206.47 3379.86,206.47 3393.64,192.7 v1(3393.64,161.29) v1(3593.64,161.29)
  Bottom Layer w5: R273.1@589.45,2037.24 v1(589.45,2087.24)
  Bottom Layer w8: U43.2@3373.64,161.29 v1(3393.64,161.29) 3393.73,161.38 3409.57,161.38 R110.1@3409.66,161.47 ; U39.2@3573.64,161.29 v1(3593.64,161.29) 3593.73,161.38 3609.57,161.38 R71.1@3609.66,161.47
Seq_1p8V: R76.1 R272.1 R274.1 U19.5 U40.2 U44.2 | length 6672.2
  L3 SIG w5: v1(626.85,2087.24) 605.68,2066.07 605.68,1852.25 436.52,1683.09 150.22,1683.09 64.75,1597.62 64.75,1020.28 38.49,994.03 38.49,967.21 92.3,913.4 215.14,913.4 226.27,902.27 226.27,876.66 245.95,856.97 245.95,804.11 268.2,781.86 268.2,659.85 309.58,618.47 592.28,618.47 666.37,544.38 666.37,220.56 810.43,76.5 1630.52,76.5 1650.18,96.16 1669.87,96.16 1672.21,98.5 2317.1,98.5 2318.18,97.42 2963.06,97.42 2970,104.36 2970,136.21 3091.6,257.8 3159.71,257.8 3211.19,309.29 3254.52,309.29 3255.05,308.76 3369.78,308.76 3396.28,282.26 3408.29,282.26 3439.66,313.62 3582.38,313.62 3584.01,311.99 3610.49,311.99 3649.27,273.21 3649.27,250.75 3660.31,239.72 3684.93,239.72 3726.53,198.12 3744.37,198.12 3767.02,175.47 3779.86,175.47 3793.64,161.7 v1(3793.64,161.29) 3833.39,121.54 3833.39,74.38 3851.08,56.7 3958.55,56.7 3978.99,77.14 3978.99,137.57 3988.53,147.1 3996.82,147.1 4004.51,154.79 4004.93,154.79 4011.43,161.29 v1(4014.95,161.29)
  Bottom Layer w5: R274.1@626.85,2037.24 v1(626.85,2087.24) ; v1(3793.64,161.29) 3793.68,161.33 3809.53,161.33 R272.1@3809.57,161.38 ; v1(4014.95,161.29) 4014.99,161.33 4030.84,161.33 R76.1@4030.88,161.38
  Bottom Layer w8: U44.2@3773.64,161.29 v1(3793.64,161.29) ; U40.2@3994.95,161.29 v1(4014.95,161.29)
Seq_LMH_Pwr: R77.1 R275.1 U19.4 U45.2 | length 5170.5
  L3 SIG w5: v1(664.25,2087.24) 645.76,2068.75 645.76,1879.6 440.25,1674.09 153.95,1674.09 73.75,1593.89 73.75,1016.55 47.49,990.3 47.49,971.07 96.16,922.4 218.87,922.4 239.84,901.43 239.84,875.81 254.95,860.7 254.95,807.83 277.2,785.59 277.2,692.09 280.32,688.97 280.32,660.46 313.31,627.47 524.5,627.47 553.76,656.73 603.46,656.73 653.11,607.07 821.11,607.07 834.77,620.73 1274.8,620.73 1279.62,615.91 1321.43,615.91 1341.87,636.35 1455.42,636.35 1690.49,871.41 2422.61,871.41 2490.48,803.54 2738.49,803.54 2751.5,790.53 2751.5,738.71 2775.84,714.37 2937.21,714.37 2998.59,775.74 v1(2998.59,839.08)
  Bottom Layer w5: R275.1@664.25,2037.24 v1(664.25,2087.24) U19.4@664.62,2087.24
  Bottom Layer w8: U45.2@2978.59,839.08 v1(2998.59,839.08) v1(2998.59,839.08) ; v1@2998.67,839.17 v1(2998.59,839.08) ; R77.1@3018.05,839.17 3018,839.12 v1(2998.59,839.08)
TDI_FMC: J9.D30 R191.2 | length 19.4
  Top Layer w10: R191.2@4746.42,879.92 4748.23,881.74 4759.89,881.74 v1(4761.42,883.27) v1@4758.43,883.27
TDO_FMC: J9.D31 R191.1 | length 21.5
  Top Layer w10: R191.1@4746.42,840.55 4746.42,839.64 4751.26,834.8 4759.89,834.8 v1(4761.42,833.27) v1@4758.43,833.27
VADJ: C185.2 C188.1 J9.E39 J9.F40 J9.G39 J9.H40 R196.2 R258.2 U34.6 U34.14 U34.15 U34.16 U35.13 | length 61.2
  Bottom Layer w8: v1(672.94,840.19) U34.6@692.94,840.19 ; v1(2546.55,967.28) 2546.55,969.25 2552.39,975.09 2554.36,975.09 2568.78,989.51 U35.13@2577.41,989.51
  other v1: 4561.42,383.27 4661.42,383.27 4611.42,433.27 4711.42,433.27 748.06,727.2 787.43,830.32 787.43,850.07 603.57,855.94
VCM_AMP: C144.2 C163.2 R139.2 U22.1 U24.1
  other v1: 2025.23,1245.12 2580.32,1796.62 2025.23,2245.12
VCORE: C177.2 C178.2 U28.12 U28.37 U28.49 U28.64 | length 167.3
  Bottom Layer w8: U28.37@67.63,1409.08 67.78,1408.92 105.32,1408.92 116.8,1397.44 v1(116.8,1397.02) ; U28.64@434.75,1697.47 435.48,1698.2 435.48,1731.33 444.56,1740.41 453.77,1740.41 v1(455.68,1742.32) ; U28.12@506.6,1409.08 v1(560.56,1409.08)
  other v1: 100.11,1697.47 100.11,1732.47
pads on no net: FID1.1 FID2.1 FID3.1 H5. H6. J9. J9.A2 J9.A3 J9.A6 J9.A7 J9.A10 J9.A11 J9.A14 J9.A15 J9.A18 J9.A19 J9.A22 J9.A23 J9.A26 J9.A27 J9.A30 J9.A31 J9.A34 J9.A35 J9.A38 J9.A39 J9.B1 J9.B4 J9.B5 J9.B8 J9.B9 J9.B12 J9.B13 J9.B16 J9.B17 J9.B20 J9.B21 J9.B24 J9.B25 J9.B28 J9.B29 J9.B32 J9.B33 J9.B36 J9.B37 J9.C2 J9.C3 J9.C6 J9.C7 J9.C22 J9.C23 J9.C26 J9.C27 J9.C39 J9.D4 J9.D5 J9.D20 J9.D21 J9.D23 J9.D24 J9.D26 J9.D27 J9.D29 J9.D33 J9.D34 J9.D36 J9.D38 J9.D40 J9.E2 J9.E3 J9.E6 J9.E7 J9.E9 J9.E10 J9.E12 J9.E13 J9.E15 J9.E16 J9.E18 J9.E19 J9.E21 J9.E22 J9.E24 J9.E25 J9.E27 J9.E28 J9.E30 J9.E31 J9.E33 J9.E34 J9.E36 J9.E37 J9.F4 J9.F5 J9.F7 J9.F8 J9.F10 J9.F11 J9.F13 J9.F14 J9.F16 J9.F17 J9.F19 J9.F20 J9.F22 J9.F23 J9.F25 J9.F26 J9.F28 J9.F29 J9.F31 J9.F32 J9.F34 J9.F35 J9.F37 J9.F38 J9.G2 J9.G3 J9.G22 J9.G24 J9.G25 J9.G27 J9.G34 J9.G36 J9.G37 J9.H1 J9.H4 J9.H5 J9.H28 J9.H29 J9.H31 J9.H32 J9.H34 J9.H35 J9.H37 J9.H38 J9.J2 J9.J3 J9.J6 J9.J7 J9.J9 J9.J10 J9.J12 J9.J13 J9.J15 J9.J16 J9.J18 J9.J19 J9.J21 J9.J22 J9.J24 J9.J25 J9.J27 J9.J28 J9.J30 J9.J31 J9.J33 J9.J34 J9.J36 J9.J37 J9.J39 J9.K1 J9.K4 J9.K5 J9.K7 J9.K8 J9.K10 J9.K11 J9.K13 J9.K14 J9.K16 J9.K17 J9.K19 J9.K20 J9.K22 J9.K23 J9.K25 J9.K27 J9.K28 J9.K29 J9.K31 J9.K32 J9.K34 J9.K35 J9.K37 J9.K38 J9.K40 J10. J10.A5 J10.A8 J10.B5 J10.B8 LBL1.0 Q2.0 U1.65@2753.94,1527.36 U1.65@2753.94,1581.3 U1.65@2753.94,1635.24 U1.65@2753.94,1689.18 U1.65@2801.97,1527.36 U1.65@2801.97,1581.3 U1.65@2801.97,1635.24 U1.65@2801.97,1689.18 U1.65@2850,1527.36 U1.65@2850,1581.3 U1.65@2850,1635.24 U1.65@2850,1689.18 U1.65@2898.03,1527.36 U1.65@2898.03,1581.3 U1.65@2898.03,1635.24 U1.65@2898.03,1689.18 U1.65@2946.06,1527.36 U1.65@2946.06,1581.3 U1.65@2946.06,1635.24 U1.65@2946.06,1689.18 U2.9 U3.12 U4.3 U4.7@1363.17,573.86 U4.7@1363.17,609.3 U5.0 U6.12 U7.4 U16.1 U17.4 U18.4 U28.21 U28.22 U28.23 U28.24 U28.29 U28.30 U28.32 U28.33 U28.34 U28.36 U28.39 U28.40 U28.41 U28.43 U28.44 U28.45 U28.46 U28.48 U28.52 U28.53 U28.54 U28.55 U28.57 U28.58 U28.59 U28.60 U31.6 U31.7 U39.5 U40.5 U41.3 U42.1 U43.5 U44.5 U45.5

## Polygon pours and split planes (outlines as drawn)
GND on Top Layer "gnd" (solid, remove dead copper, pour order 91): 0,1 5000,1 5000,2715.5 0,2715.5
NetF2_3 on Top Layer "TOP_LAYER_NETF2_3_P000" (solid, remove dead copper, pour order 0): 492.25,745.38 0,745.38 0,0.5 894.97,0.5 894.97,220.99 651.21,220.99 492.25,379.95
GND on L5 PWR "gnd" (solid, remove dead copper, pour order 131): 0,0.5 5000,0.5 5000,2715 0,2715
MainPwr on L5 PWR "1" (solid, pour order 101): 314.52,1872.47 690.63,1872.47 690.63,1212.37 690.63,401.27 1745.84,401.27 1745.84,727.2 1005,727.2 1005,2715 314.52,2715
12V_FMC on L5 PWR "L5 PWR-12V_FMC" (solid, pour order 99): 1328.85,0 1985.85,0 1985.85,0.5 5000,0.5 5000,697.68 4445,697.68 4445,327.49 1328.85,327.49
DVDD18 on L5 PWR "gnd" (solid, remove dead copper, pour order 104): 3995,795 3995,1540 3010,1540 3010,1710 4155,1710 4155,795
VCORE on L5 PWR "L10 PWR-VCORE" (solid, pour order 110): 593.71,1388.68 593.71,1618.19 495.12,1618.19 495.12,1772.94 495,1772.94 495,1775 90,1775 90,1665 320,1665 320,1474.75 105.58,1474.75 105.58,1388.68
DVDD12 on L5 PWR "gnd" (solid, remove dead copper, pour order 117): 3540,780 3700,780 3700,1485 3015,1485 2945,1485 2945,1740 3090,1740 3090,1855 2870,1855 2870,1160 3540,1160
AVDD12 on L5 PWR "gnd" (solid, remove dead copper, pour order 118): 3470,895 2810,895 2810,1900 2685,1900 2685,1750 2730,1750 2730,1675 2665,1675 2665,1585 2735,1585 2735,1490 2690,1490 2690,695 3470,695
AVDD18 on L5 PWR "gnd" (solid, remove dead copper, pour order 124): 3775,915 3930,915 3930,410 2450,410 2450,1900 2685,1900 2685,1750 2730,1750 2730,1675 2665,1675 2665,1585 2735,1585 2735,1490 2690,1490 2690,695 3775,695
-1p1V_LMH on L5 PWR "L5_PWR_-1P1V_LMH_P127" (solid, pour order 127): 1875,2155 1875,2290 1980,2290 1980,2360 1740,2360 1740,2155 1830,2155
-1p1V_LMH on L5 PWR "L5_PWR_-1P1V_LMH_P128" (solid, pour order 128): 1875,1155 1875,1290 1980,1290 1980,1360 1740,1360 1740,1155 1830,1155
GND on L8 PWR "gnd" (solid, remove dead copper, pour order 139): 0,0 5000,0 5000,2714.5 0,2714.5
VADJ on L8 PWR "1" (solid, pour order 136): 558.2,895.37 558.2,650.57 2717.69,650.57 2717.69,839.71 3549.82,839.71 3549.82,350.97 4743.3,350.97 4743.3,1111.11 2447.03,1111.11 2447.03,802.91 1390,802.91 1390,895.37
-1p1V_LMH on L8 PWR "L8 PWR--1p2V_LMH" (solid, pour order 122): 1390,802.91 2221.3,802.91 2221.3,933.09 1875,933.09 1875,2319.71 1390,2319.71
4p3V_LDO on L8 PWR "1" (solid, pour order 135): 2087.83,0 3549.82,0 3549.82,863.88 2717.69,863.88 2717.69,650.57 3329.82,650.57 3329.82,208.99 2950.09,208.99 2950.09,444.63 2087.83,444.63 2087.83,330.21
MainPwr on L8 PWR "L8 PWR-MainPwr" (solid, remove dead copper, pour order 65): 2950.09,208.99 3329.82,208.99 3329.82,650.57 1330,650.57 1330,444.63 2950.09,444.63
3p3V_AUX on L8 PWR "1" (solid, pour order 83): 4739.77,805.65 4924.71,805.65 4924.71,325.73 4849.42,325.73 4849.42,229.77 4625,229.77 4625,116.04 4499.48,116.04 4499.48,350.97 4740.35,350.97
3p3V_EEPROM on L8 PWR "gnd" (solid, remove dead copper, pour order 70): 4625,229.77 4625,0 5000.94,0 5000.94,325.73 4849.42,325.73 4849.42,229.77
3p9V_LMH on L8 PWR "L8 PWR-3p9V_LMH" (solid, pour order 134): 1875,933.09 2221.3,933.09 2221.3,802.91 2447.03,802.91 2447.03,2335 1875,2335 1875,1000.91
VCM_AMP on L8 PWR "L8 PWR-VCM_AMP" (solid, remove dead copper, pour order 115): 2613.12,1190 2613.12,1762.34 2613.12,2255 2015,2255 2015,2200 2340,2200 2340,1274.33 2010,1274.33 2010,1190
3p3V_Utility on L10 PWR "L10 PWR-3p3V_Utility" (solid, pour order 125): 0,0.5 5000,0.5 5000,2715 0,2715
1p8V_Utility on L10 PWR "L10 PWR-1p8V_Utility" (solid, remove dead copper, pour order 108): 395.51,1040.63 395.51,1136.38 281.32,1136.38 281.32,940 455.68,940 455.68,534.5 1355,534.5 1355,979.51 2805,979.51 2805,2147.05 4430,2147.05 4430,2715 2400,2715 2400,1650 620,1650 620,1430 850,1430 850,1055 607.5,1055 607.5,1040.63
2p3V_LDO on L10 PWR "L10_PWR_2P3V_LDO_P086" (solid, pour order 86): 3050,142.95 3050,0.5 4085.31,0.5 4085.31,142.95
GND on L2 GND "gnd" (solid, remove dead copper, pour order 56): 0,0.5 5000,0.5 5000,2715 0,2715
GND on L4 GND "gnd" (solid, remove dead copper, pour order 69): 0,0.5 5000,0.5 5000,2715 0,2715
GND on L6 GND "gnd" (solid, remove dead copper, pour order 71): 0,0.5 5000,0.5 5000,2715 0,2715
GND on L7 GND "gnd" (solid, remove dead copper, pour order 72): 0,0.5 5000,0.5 5000,2715 0,2715
GND on L9 GND "gnd" (solid, remove dead copper, pour order 73): 0,0.5 5000,0.5 5000,2715 0,2715
GND on L11 GND "gnd" (solid, remove dead copper, pour order 74): 0,0.5 5000,0.5 5000,2715 0,2715
GND on L3 SIG "gnd" (solid, remove dead copper, pour order 138): 0,0 5000,0 5000,2714.5 0,2714.5
GND on Bottom Layer "gnd" (solid, remove dead copper, pour order 129): 0,1 5000,1 5000,2715.5 0,2715.5

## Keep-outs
Keep-Out Layer:
  text ".Layer_Name" at 577,-858.49 h60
